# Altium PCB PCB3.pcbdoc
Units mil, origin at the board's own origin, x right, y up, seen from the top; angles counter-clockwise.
Board outline 9260 x 3292.5 mil, 4 copper layers (Top Layer, Inner1, Inner2, Bottom Layer); 89 components, 217 nets, 603 pads, 96 vias.
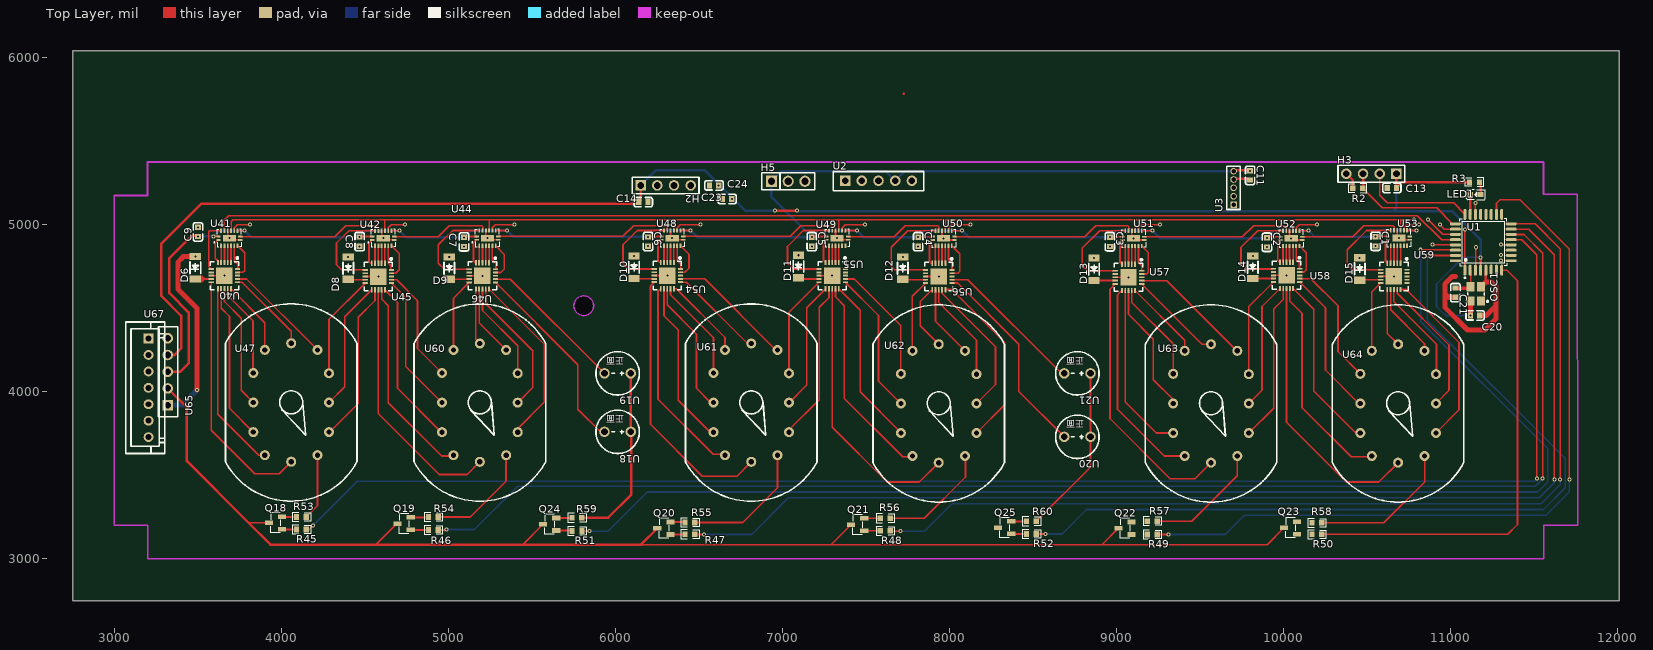
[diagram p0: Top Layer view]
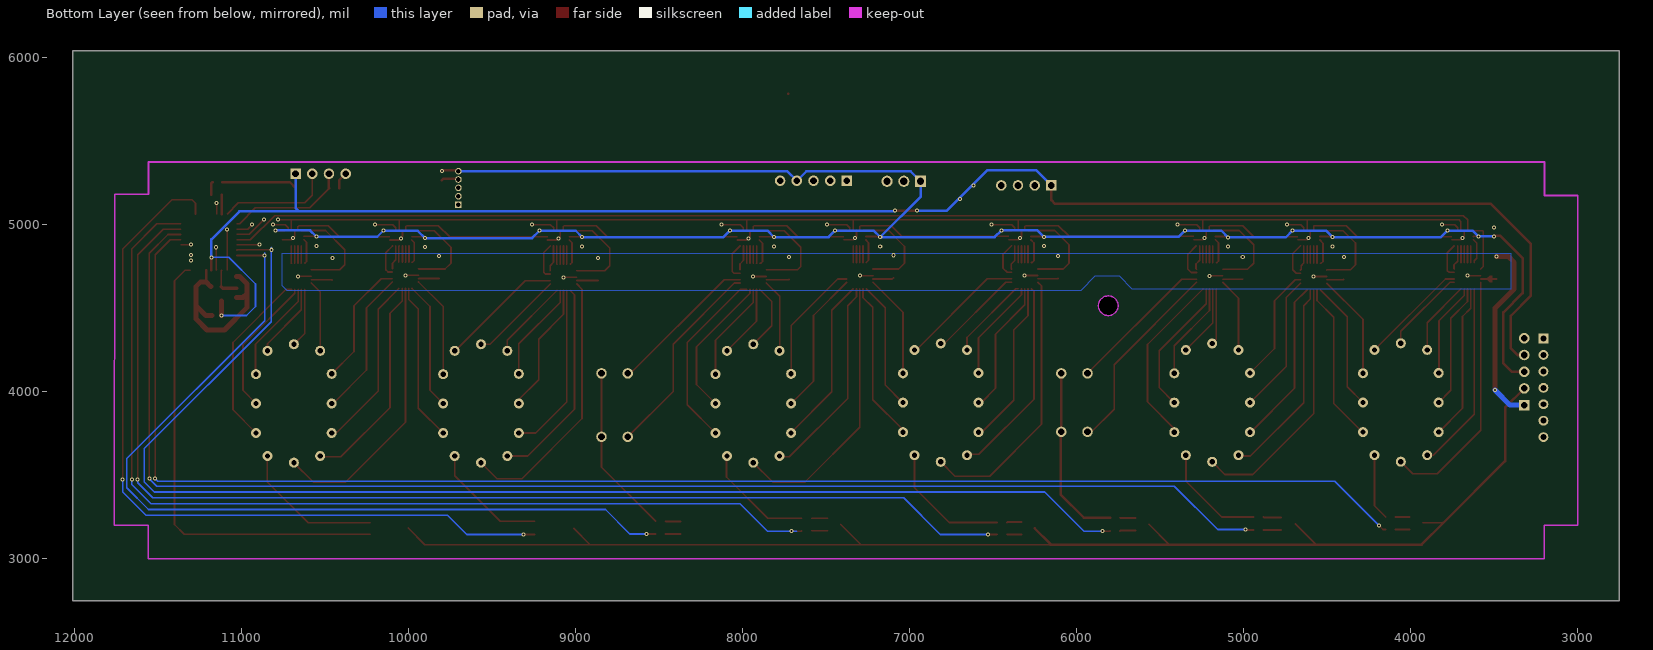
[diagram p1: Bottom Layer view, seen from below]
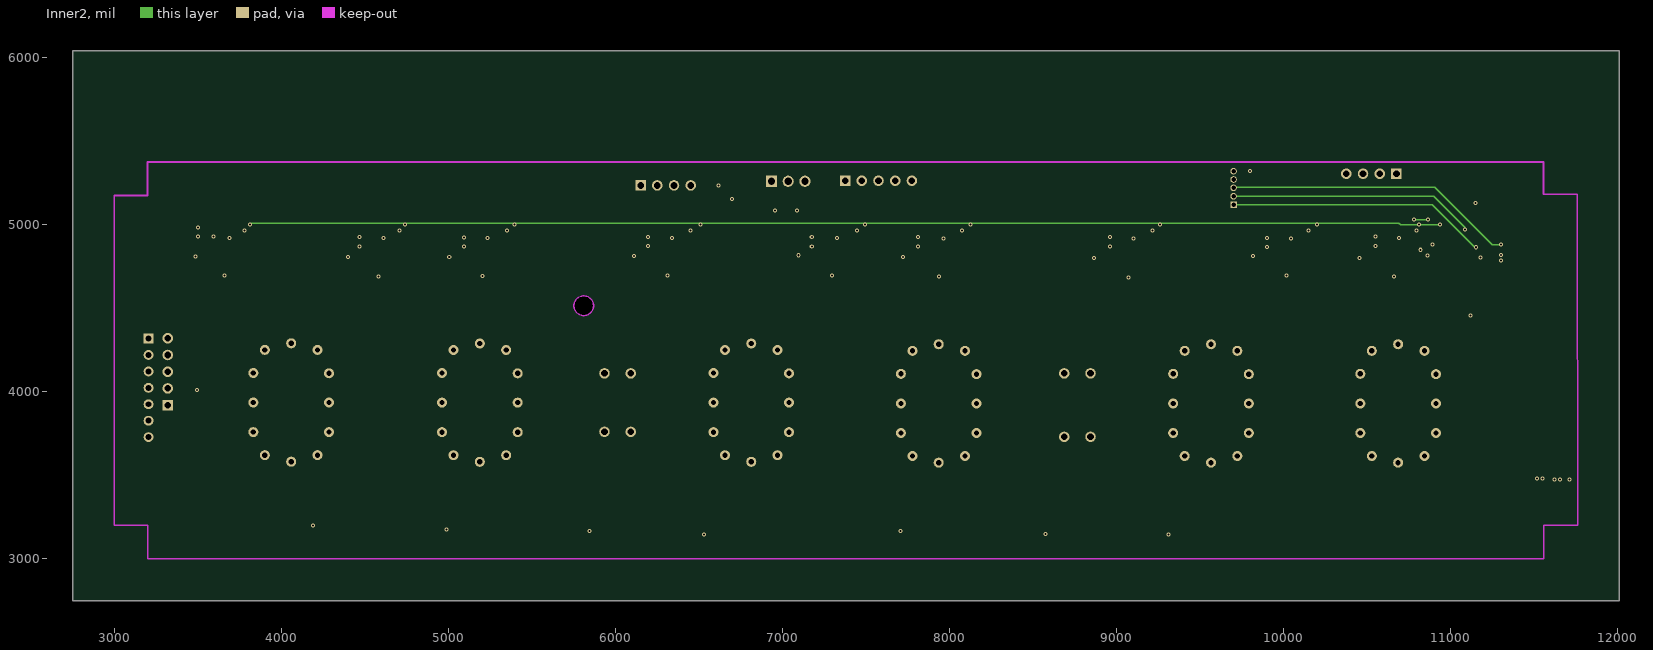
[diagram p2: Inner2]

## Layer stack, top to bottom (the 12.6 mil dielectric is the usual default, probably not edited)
Top Layer: signal copper (thickness not stored)
Dielectric: dielectric 12.6, FR-4, Dk 4.8
Inner1: signal copper (thickness not stored)
Dielectric: dielectric 12.6, FR-4, Dk 4.8
Inner2: signal copper (thickness not stored)
Dielectric: dielectric 12.6, FR-4, Dk 4.8
Bottom Layer: signal copper (thickness not stored)

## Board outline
12010,2750 2750,2750 2750,6042.5 12010,6042.5
cut-out: 5869.06,4515 cw(c5810,4515) 5750.94,4515 cw(c5810,4515)

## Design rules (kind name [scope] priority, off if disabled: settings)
BoardOutlineClearance copperThickness1oz [All] p0: genericclearance=10 ignorepadtopadclearanceinfootprint=FALSE except(0: Arc-SplitContinuation Track-SplitContinuation SMDPad-SplitContinuation THPad-SplitContinuation Via-SplitContinuation Fill-SplitContinuation Poly-SplitContinuation Region-SplitContinuation Text-SplitContinuation; 6: SMDPad-CutoutEdge THPad-CutoutEdge Via-CutoutEdge Fill-CutoutEdge Region-CutoutEdge; 11.8: Track-OutlineEdge SMDPad-OutlineEdge THPad-OutlineEdge Via-OutlineEdge Fill-OutlineEdge Region-OutlineEdge Poly-OutlineEdge Text-OutlineEdge Track-CutoutEdge)
BoardOutlineClearance copperThickness2oz [All] p0: genericclearance=10 ignorepadtopadclearanceinfootprint=FALSE except(0: Arc-SplitContinuation Track-SplitContinuation SMDPad-SplitContinuation THPad-SplitContinuation Via-SplitContinuation Fill-SplitContinuation Poly-SplitContinuation Region-SplitContinuation Text-SplitContinuation; 6: SMDPad-CutoutEdge THPad-CutoutEdge Via-CutoutEdge Fill-CutoutEdge Region-CutoutEdge; 11.8: Track-OutlineEdge SMDPad-OutlineEdge THPad-OutlineEdge Via-OutlineEdge Fill-OutlineEdge Region-OutlineEdge Poly-OutlineEdge Text-OutlineEdge Track-CutoutEdge)
Clearance copperThickness1oz [(InNet('GND') OR InNet('$1N6169') OR InNet('$1N6665') OR InNet('$1N6235') OR InNet('$1N6836') OR InNet('$1N6302') OR InNet('$1N6839') OR InNet('$1N6369') OR InNet('$1N6842') OR InNet('$1N6436') OR InNet('$1N6854') OR InNet('$1N6503') OR InNet('$1N6851') OR InNet('$1N6570') OR InNet('$1N6848') OR InNet('$1N6637') OR InNet('$1N6845') OR InNet('+5V') OR InNet('$1N7409') OR InNet('ADOT') OR InNet('NIX_A9') OR InNet('NIX_ADOT') OR InNet('$1N7759') OR InNet('$1N7768') OR InNet('NIX_A1') OR InNet('NIX_A2') OR InNet('NIX_A3') OR InNet('NIX_A4') OR InNet('NIX_A5') OR InNet('NIX_A6') OR InNet('NIX_A7') OR InNet('NIX_A8') OR InNet('A2') OR InNet('A3') OR InNet('A4') OR InNet('A5') OR InNet('A6') OR InNet('A7') OR InNet('$1N7662') OR InNet('NIX_A0') OR InNet('A0') OR InNet('A1') OR InNet('$1N7281') OR InNet('A8') OR InNet('A9') OR InNet('170V') OR InNet('SWITCH1') OR InNet('SWITCH2') OR InNet('SWITCH3') OR InNet('SWITCH4') OR InNet('SWITCH5') OR InNet('SWITCH6') OR InNet('COLON1') OR InNet('COLON2') OR InNet('A_HV') OR InNet('B_HV') OR InNet('C_HV') OR InNet('D_HV') OR InNet('E_HV') OR InNet('F_HV') OR InNet('G_HV') OR InNet('H_HV') OR InNet('CLK') OR InNet('CS') OR InNet('MOSI') OR InNet('BDOT') OR InNet('B1') OR InNet('B2') OR InNet('B3') OR InNet('B4') OR InNet('B7') OR InNet('B8') OR InNet('B9') OR InNet('B0') OR InNet('CDOT') OR InNet('C1') OR InNet('$1N12092') OR InNet('B5') OR InNet('B6') OR InNet('NIX_BDOT') OR InNet('NIX_B1') OR InNet('NIX_B2') OR InNet('NIX_B3') OR InNet('NIX_B4') OR InNet('NIX_B5') OR InNet('NIX_B6') OR InNet('NIX_B7') OR InNet('NIX_B8') OR InNet('NIX_B9') OR InNet('NIX_B0') OR InNet('NIX_CDOT') OR InNet('NIX_C1') OR InNet('C4') OR InNet('C5') OR InNet('C6') OR InNet('C7') OR InNet('C8') OR InNet('C9') OR InNet('$1N12107') OR InNet('C2') OR InNet('C3') OR InNet('D1') OR InNet('D2') OR InNet('D3') OR InNet('D4') OR InNet('D5') OR InNet('D6') OR InNet('$1N12114') OR InNet('C0') OR InNet('DDOT') OR InNet('D9') OR InNet('D0') OR InNet('EDOT') OR InNet('E1') OR InNet('E2') OR InNet('E3') OR InNet('$1N12123') OR InNet('D7') OR InNet('D8') OR InNet('E6') OR InNet('E7') OR InNet('E8') OR InNet('E9') OR InNet('E0') OR InNet('FDOT') OR InNet('$1N12132') OR InNet('E4') OR InNet('E5') OR InNet('F3') OR InNet('F4') OR InNet('F5') OR InNet('F6') OR InNet('F7') OR InNet('F8') OR InNet('$1N12137') OR InNet('F1') OR InNet('F2') OR InNet('F9') OR InNet('F0') OR InNet('$1N10205') OR InNet('$1N10207') OR InNet('$1N10209') OR InNet('$1N10723') OR InNet('$1N10725') OR InNet('$1N10727') OR InNet('+3.3V') OR InNet('RADER_RX') OR InNet('OSC_IN') OR InNet('RADER') OR InNet('NRST') OR InNet('LIGHT_ADC') OR InNet('BLE_TX') OR InNet('BLE_RX') OR InNet('SPI_MOSI') OR InNet('RADER_TX') OR InNet('POWER') OR InNet('I2C1_SCL') OR InNet('SPI_CS') OR InNet('I2C1_SDA') OR InNet('INFRARED-RAY') OR InNet('LED') OR InNet('SWDIO') OR InNet('SWCLK') OR InNet('DS3231') OR InNet('$2N1508') OR InNet('NIX_G0') OR InNet('NIX_G1') OR InNet('NIX_H0') OR InNet('NIX_H1') OR InNet('G0') OR InNet('G1') OR InNet('H0') OR InNet('H1') OR InNet('NIX_C2') OR InNet('NIX_C3') OR InNet('NIX_C4') OR InNet('NIX_C5') OR InNet('NIX_C6') OR InNet('NIX_C7') OR InNet('NIX_C8') OR InNet('NIX_C9') OR InNet('NIX_C0') OR InNet('NIX_DDOT') OR InNet('NIX_D1') OR InNet('NIX_D2') OR InNet('NIX_D3') OR InNet('NIX_D4') OR InNet('NIX_D5') OR InNet('NIX_D6') OR InNet('NIX_D7') OR InNet('NIX_D8') OR InNet('NIX_D9') OR InNet('NIX_D0') OR InNet('NIX_EDOT') OR InNet('NIX_E1') OR InNet('NIX_E2') OR InNet('NIX_E3') OR InNet('NIX_E4') OR InNet('NIX_E5') OR InNet('NIX_E6') OR InNet('NIX_E7') OR InNet('NIX_E8') OR InNet('NIX_E9') OR InNet('NIX_E0') OR InNet('NIX_FDOT') OR InNet('NIX_F1') OR InNet('NIX_F2') OR InNet('NIX_F3') OR InNet('NIX_F4') OR InNet('NIX_F5') OR InNet('NIX_F6') OR InNet('NIX_F7') OR InNet('NIX_F8') OR InNet('NIX_F9') OR InNet('NIX_F0') OR InNet('170_GND') OR InNet('SPI_SCK'))] p1: gap=7 ignorepadtopadclearanceinfootprint=FALSE except(4: Track-Track; 6: Track-SMDPad SMDPad-SMDPad Track-THPad SMDPad-THPad THPad-THPad Track-Via SMDPad-Via THPad-Via Via-Via Track-Fill SMDPad-Fill THPad-Fill Via-Fill Fill-Fill SMDPad-Region THPad-Region Via-Region Fill-Region Region-Region Track-Poly SMDPad-Poly THPad-Poly Via-Poly Fill-Poly Poly-Poly Track-Text SMDPad-Text THPad-Text Via-Text Fill-Text Region-Text Poly-Text Text-Text Track-Hole SMDPad-Hole THPad-Hole Via-Hole Fill-Hole Region-Hole Poly-Hole Text-Hole; 11.8: Track-Region Region-Poly Track-Sheet SMDPad-Sheet THPad-Sheet Via-Sheet Fill-Sheet Region-Sheet Poly-Sheet Text-Sheet Sheet-Hole)
Clearance copperThickness2oz [All] p1: gap=7 ignorepadtopadclearanceinfootprint=FALSE except(6: Track-SMDPad SMDPad-SMDPad Track-THPad SMDPad-THPad THPad-THPad Track-Via SMDPad-Via THPad-Via Via-Via Track-Fill SMDPad-Fill THPad-Fill Via-Fill Fill-Fill SMDPad-Region THPad-Region Via-Region Fill-Region Region-Region Track-Poly SMDPad-Poly THPad-Poly Via-Poly Fill-Poly Poly-Poly Track-Text SMDPad-Text THPad-Text Via-Text Fill-Text Region-Text Poly-Text Text-Text Track-Hole SMDPad-Hole THPad-Hole Via-Hole Fill-Hole Region-Hole Poly-Hole Text-Hole; 8: Track-Track; 11.8: Track-Region Region-Poly Track-Sheet SMDPad-Sheet THPad-Sheet Via-Sheet Fill-Sheet Region-Sheet Poly-Sheet Text-Sheet Sheet-Hole)
DiffPairsRouting differentialPair [All] p1: maxuncoupledlength=10 minlimit=6 maxlimit=6 mostfreqgap=6 toplayer_minwidth=5 toplayer_prefwidth=10 toplayer_maxwidth=100 bottomlayer_minwidth=5 bottomlayer_prefwidth=10 bottomlayer_maxwidth=100 midlayer1_minwidth=5 midlayer1_prefwidth=10 midlayer1_maxwidth=100 midlayer2_minwidth=5 midlayer2_prefwidth=10 midlayer2_maxwidth=100
PasteMaskExpansion pasteMaskExpansion [All] p1: expansion=0
PlaneConnect innerPlane [All] p1: planeconnectstyle=Relief reliefexpansion=20 reliefentries=4 reliefconductorwidth=10 reliefairgap=10
PolygonConnect copperRegion [All] p1: connectstyle=Relief reliefentries=4 reliefconductorwidth=10 polygonreliefangle="90 Angle" airgapwidth=10
RoutingVias viaSize [All] p1: viastyle="Through Hole" holewidth=12.0078 minholewidth=11.811 maxholewidth=248.0314 width=24.0158 minwidth=19.685 maxwidth=393.7008
SolderMaskExpansion solderMaskExpansion [All] p1: useseparateexpansions=TRUE expansion=2 expansionbottom=2
Width copperThickness1oz [All] p1: maxlimit=100 minlimit=5 preferedwidth=10
Width copperThickness2oz [All] p1: maxlimit=100 minlimit=8 preferedwidth=10

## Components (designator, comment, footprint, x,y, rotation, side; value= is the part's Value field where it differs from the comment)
C1 "CAP_0603" c0603 10550.22,4900.34 r270 top
C2 "CAP_0603" c0603 9900,4894.57 r270 top
C3 "CAP_0603" c0603 8959.25,4897.68 r270 top
C4 "CAP_0603" c0603 7812.28,4898 r270 top
C5 "CAP_0603" c0603 7175,4898 r270 top
C6 "CAP_0603" c0603 6195,4898.94 r270 top
C7 "CAP_0603" c0603 5093.22,4896.89 r270 top
C8 "CAP_0603" c0603 4468.27,4898.09 r270 top
C9 "CAP_0603" c0603 3500.75,4957.01 r90 top
C11 "CC0603KRX7R9BB104" c0603 9799.25,5294.66 r270 top
C13 "CC0603KRX7R9BB104" c0603 10647.09,5220 r180 top
C14 "CC0603KRX7R9BB104" c0603 6166.54,5135 r0 top
C20 "CC0603KRX7R9BB104" c0603 11146.56,4456.76 r0 top
C21 "CC0603KRX7R9BB104" c0603 11027.99,4592.82 r270 top
C23 "CC0603KRX7R9BB104" c0603 6668.68,5153.88 r0 top
C24 "CC0603KRX7R9BB104" c0603 6590,5235 r0 top
D6 "ZMM51" LL-34_L3.5-W1.5-RD 3485,4742.24 r90 top
D8 "ZMM51" LL-34_L3.5-W1.5-RD 4400,4740 r90 top
D9 "ZMM51" LL-34_L3.5-W1.5-RD 5005,4740 r90 top
D10 "ZMM51" LL-34_L3.5-W1.5-RD 6111.42,4745 r90 top
D11 "ZMM51" LL-34_L3.5-W1.5-RD 7095,4750 r90 top
D12 "ZMM51" LL-34_L3.5-W1.5-RD 7720,4740 r90 top
D13 "ZMM51" LL-34_L3.5-W1.5-RD 8865,4733.13 r90 top
D14 "ZMM51" LL-34_L3.5-W1.5-RD 9815,4745 r90 top
D15 "ZMM51" LL-34_L3.5-W1.5-RD 10455,4735 r90 top
H2 "排针" SIP-2.54MM-4P-CJT-H8.54 6300.49,5235 r180 top
H3 "排针" SIP-2.54MM-4P-CJT-H8.54 10525,5305 r0 top
H5 "PZ254V-11-03P" HDR-TH_3P-P2.54-V-M 7033.84,5260 r0 top
LED1 "NCD0603R1_C84263" LED0603-RD_RED 11147.74,5180 r0 top
OSC1 "OT2EL4C4JI-111OLP-8M" OSC-SMD_4P-L3.2-W2.5-BL-1 11150.5,4585.77 r90 top
Q18 "13001_C2904842" SOT-23-3_L2.9-W1.3-P1.90-LS2.4-BR 3965,3215 r0 top
Q19 "13001_C2904842" SOT-23-3_L2.9-W1.3-P1.90-LS2.4-BR 4735,3210.16 r0 top
Q20 "13001_C2904842" SOT-23-3_L2.9-W1.3-P1.90-LS2.4-BR 6290,3182.98 r0 top
Q21 "13001_C2904842" SOT-23-3_L2.9-W1.3-P1.90-LS2.4-BR 7450,3205 r0 top
Q22 "13001_C2904842" SOT-23-3_L2.9-W1.3-P1.90-LS2.4-BR 9050,3182.98 r0 top
Q23 "13001_C2904842" SOT-23-3_L2.9-W1.3-P1.90-LS2.4-BR 10040.78,3185 r0 top
Q24 "13001_C2904842" SOT-23-3_L2.9-W1.3-P1.90-LS2.4-BR 5605.8,3206.69 r0 top
Q25 "13001_C2904842" SOT-23-3_L2.9-W1.3-P1.90-LS2.4-BR 8330,3186.3 r0 top
R2 "0805W8F1002T5E_C17414" r0603 10442.93,5217.87 r0 top
R3 "0805W8F1002T5E_C17414" r0603 11142.53,5255 r0 top
R45 "Res_0603" r0603 4120.06,3175 r180 top
R46 "Res_0603" r0603 4910,3172.6 r180 top
R47 "Res_0603" r0603 6445.8,3147.35 r180 top
R48 "Res_0603" r0603 7615,3167.05 r180 top
R49 "Res_0603" r0603 9213.04,3145.58 r180 top
R50 "Res_0603" r0603 10198.67,3146.37 r180 top
R51 "Res_0603" r0603 5769.61,3166.06 r180 top
R52 "Res_0603" r0603 8490,3148.9 r180 top
R53 "Res_0603" r0603 4120.06,3250.63 r180 top
R54 "Res_0603" r0603 4910,3249.96 r180 top
R55 "Res_0603" r0603 6445.8,3217.15 r180 top
R56 "Res_0603" r0603 7615,3243.3 r180 top
R57 "Res_0603" r0603 9213.04,3225.38 r180 top
R58 "Res_0603" r0603 10198.67,3215 r180 top
R59 "Res_0603" r0603 5769.23,3245.86 r180 top
R60 "Res_0603" r0603 8490,3224.62 r180 top
U1 "STM32G070KBT6" LQFP-32_L7.0-W7.0-P0.80-LS9.0-BL 11195,4894.57 r0 top
U2 "2.54mm1*5" 2.54mm1*5 7574.51,5263.03 r0 top
U3 "FH1.27-01-5PZD" HDR-TH_5P-P1.27-V-M 9700,5220.54 r90 top
U18 "氖泡" 6*13氖泡 6012.99,3760 r180 top
U19 "氖泡" 6*13氖泡 6012.99,4110 r180 top
U20 "氖泡" 6*13氖泡 8765,3730 r180 top
U21 "氖泡" 6*13氖泡 8765,4110 r180 top
U40 "ULN2803A_C493377" QFN-20_L4.0-W4.0-P0.50-BL-EP 3659.33,4695 r180 top
U41 "74HC595BQ,115" DHVQFN-16_L3.5-W2.5-P0.50-BL-EP 3688.86,4919.05 r0 top
U42 "74HC595BQ,115" DHVQFN-16_L3.5-W2.5-P0.50-BL-EP 4610,4919.05 r0 top
U44 "74HC595BQ,115" DHVQFN-16_L3.5-W2.5-P0.50-BL-EP 5233.81,4919.6 r0 top
U45 "ULN2803A_C493377" QFN-20_L4.0-W4.0-P0.50-BL-EP 4580.47,4689.72 r180 top
U46 "ULN2803A_C493377" QFN-20_L4.0-W4.0-P0.50-BL-EP 5203.62,4694.06 r180 top
U47 "IN12" IN12 4058.8,3935.63 r0 top
U48 "74HC595BQ,115" DHVQFN-16_L3.5-W2.5-P0.50-BL-EP 6339.68,4920 r0 top
U49 "74HC595BQ,115" DHVQFN-16_L3.5-W2.5-P0.50-BL-EP 7327.11,4919.33 r0 top
U50 "74HC595BQ,115" DHVQFN-16_L3.5-W2.5-P0.50-BL-EP 7964.25,4918.67 r0 top
U51 "74HC595BQ,115" DHVQFN-16_L3.5-W2.5-P0.50-BL-EP 9101.1,4918.35 r0 top
U52 "74HC595BQ,115" DHVQFN-16_L3.5-W2.5-P0.50-BL-EP 10045,4918.35 r0 top
U53 "74HC595BQ,115" DHVQFN-16_L3.5-W2.5-P0.50-BL-EP 10690,4920.16 r0 top
U54 "ULN2803A_C493377" QFN-20_L4.0-W4.0-P0.50-BL-EP 6310.15,4695.42 r180 top
U55 "ULN2803A_C493377" QFN-20_L4.0-W4.0-P0.50-BL-EP 7297.58,4695 r180 top
U56 "ULN2803A_C493377" QFN-20_L4.0-W4.0-P0.50-BL-EP 7935.32,4690 r180 top
U57 "ULN2803A_C493377" QFN-20_L4.0-W4.0-P0.50-BL-EP 9070.91,4685 r180 top
U58 "ULN2803A_C493377" QFN-20_L4.0-W4.0-P0.50-BL-EP 10017.32,4696.79 r180 top
U59 "ULN2803A_C493377" QFN-20_L4.0-W4.0-P0.50-BL-EP 10659.81,4690.5 r180 top
U60 "IN12" IN12 5188,3935 r0 top
U61 "IN12" IN12 6812.88,3935 r0 top
U62 "IN12" IN12 7935,3930 r0 top
U63 "IN12" IN12 9565,3930 r0 top
U64 "IN12" IN12 10685,3930 r0 top
U65 "2.54mm1*5" 2.54mm1*5 3320,4120 r90 top
U67 "HX 2.54mm-7P ZZ" CONN-TH_7P-P2.50_HX-2.54MM-7P-ZZ 3205,4023.54 r270 top

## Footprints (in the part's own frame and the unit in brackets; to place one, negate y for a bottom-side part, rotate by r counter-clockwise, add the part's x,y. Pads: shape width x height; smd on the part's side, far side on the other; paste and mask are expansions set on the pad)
2.54mm1*5 [mm]
  rect 1.6x1.6 hole 1: 1(-5.08,0)
  round 1.6 hole 1: 2(-2.54,0) 3(0,0) 4(2.54,0) 5(5.08,0)
  silkscreen extent -6.86,-1.52 6.86,1.4
6*13氖泡 [mm]
  round 1.6 hole 1: 1(-2,0) 2(2,0)
  silkscreen extent -3.3,-3.3 3.3,3.3
c0603 [mm]
  rect 0.8x0.9 smd: 1(-0.7,0) 2(0.7,0)
  silkscreen extent -1.41,-0.71 1.39,0.72
CONN-TH_7P-P2.50_HX-2.54MM-7P-ZZ [mm]
  rect 1.5x1.5 hole 0.9: 1(-7.5,0)
  round 1.5 hole 0.9: 2(-5,0) 3(-2.5,0) 4(0,0) 5(2.5,0) 6(5,0) 7(7.5,0)
  silkscreen extent -10,-3.46 10,2.44
DHVQFN-16_L3.5-W2.5-P0.50-BL-EP [mm]
  rect 0.665x0.28 smd: 1(-1.658,-0.25) 8(1.658,-0.25) 9(1.658,0.25) 16(-1.658,0.25)
  rect 0.28x0.665 smd: 2(-1.25,-1.157) 3(-0.75,-1.157) 4(-0.25,-1.157) 5(0.25,-1.157) 6(0.75,-1.157) 7(1.25,-1.157) 10(1.25,1.157) 11(0.75,1.157) 12(0.25,1.157) 13(-0.25,1.157) 14(-0.75,1.157) 15(-1.25,1.157)
  rect 2x1 smd: 17(0,0)
  silkscreen extent -2.36,-1.33 1.83,1.33
HDR-TH_3P-P2.54-V-M [mm]
  rect 1.7x1.7 hole 1.1: 1(-2.54,0)
  round 1.7 hole 1.1: 2(0,0) 3(2.54,0)
  silkscreen extent -4.02,-1.27 4.02,1.27
HDR-TH_5P-P1.27-V-M [mm]
  rect 1x1 hole 0.7: 1(-2.54,0)
  round 1 hole 0.7: 2(-1.27,0) 3(0,0) 4(1.27,0) 5(2.54,0)
  silkscreen extent -3.3,-1.02 3.3,1.02
IN12 [mil]
  round 60 hole 31.5: 0(226.4,-177.2) 1(-157.5,-315) 2(-226.4,-177.2) 3(-226.4,0) 4(-226.4,177.2) 5(-157.5,315) 6(0,354.3) 7(157.5,315) 8(226.4,175) 9(226.4,0) DOT(0,-354.3) HV(157.5,-315)
  silkscreen extent -394,-591 394,591
LED0603-RD_RED [mm]
  rect 0.8x0.8 smd: 1(-0.8,-0.003) 2(0.8,0.003)
  silkscreen extent -1.49,-0.75 1.39,0.76
LL-34_L3.5-W1.5-RD [mm]
  rect 1.1x1.7 smd: 1(-1.7,0) 2(1.7,0)
  silkscreen extent -0.9,-0.8 0.9,0.8
LQFP-32_L7.0-W7.0-P0.80-LS9.0-BL [mm]
  oval 0.448x1.684 smd: 1(-2.8,-4.242) 2(-2,-4.242) 3(-1.2,-4.242) 4(-0.4,-4.242) 5(0.4,-4.242) 6(1.2,-4.242) 7(2,-4.242) 8(2.8,-4.242) 17(2.8,4.242) 18(2,4.242) 19(1.2,4.242) 20(0.4,4.242) 21(-0.4,4.242) 22(-1.2,4.242) 23(-2,4.242) 24(-2.8,4.242)
  oval 1.684x0.448 smd: 9(4.242,-2.8) 10(4.242,-2) 11(4.242,-1.2) 12(4.242,-0.4) 13(4.242,0.4) 14(4.242,1.2) 15(4.242,2) 16(4.242,2.8) 25(-4.242,2.8) 26(-4.242,2) 27(-4.242,1.2) 28(-4.242,0.4) 29(-4.242,-0.4) 30(-4.242,-1.2) 31(-4.242,-2) 32(-4.242,-2.8)
  silkscreen extent -3.58,-5.48 3.58,3.58
OSC-SMD_4P-L3.2-W2.5-BL-1 [mm]
  rect 1.4x1.2 smd: 1(-1.1,-0.8) 2(1.1,-0.8) 3(1.1,0.8) 4(-1.1,0.8)
  silkscreen extent -1.27,-1.91 0.17,1.25
QFN-20_L4.0-W4.0-P0.50-BL-EP [mm]
  rect 0.28x0.8 smd: 1(-1,-2) 2(-0.5,-2) 3(0,-2) 4(0.5,-2) 5(1,-2) 11(1,2) 12(0.5,2) 13(0,2) 14(-0.5,2) 15(-1,2)
  rect 0.8x0.28 smd: 6(2,-1) 7(2,-0.5) 8(2,0) 9(2,0.5) 10(2,1) 16(-2,1) 17(-2,0.5) 18(-2,0) 19(-2,-0.5) 20(-2,-1)
  rect 2.5x2.5 smd: 21(0,0)
  silkscreen extent -2.15,-2.82 2.15,2.15
r0603 [mil]
  rect 31.75x34.02 smd: 1(-29.66,0) 2(29.66,0)
  silkscreen extent -55,-26 55,26
SIP-2.54MM-4P-CJT-H8.54 [mm]
  rect 1.6x1.6 hole 1.02: 1(3.81,0)
  round 1.6 hole 1.02: 2(1.27,0) 3(-1.27,0) 4(-3.81,0)
  silkscreen extent -5.08,-1.27 5.08,1.27
SOT-23-3_L2.9-W1.3-P1.90-LS2.4-BR [mm]
  rect 1.25x0.7 smd: 1(1,-0.95) 2(1,0.95) 3(-1,0)
  silkscreen extent -0.73,-1.53 0.73,1.53

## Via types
v1: diameter 24.02, hole 12.01, Top Layer to Bottom Layer, 96 vias

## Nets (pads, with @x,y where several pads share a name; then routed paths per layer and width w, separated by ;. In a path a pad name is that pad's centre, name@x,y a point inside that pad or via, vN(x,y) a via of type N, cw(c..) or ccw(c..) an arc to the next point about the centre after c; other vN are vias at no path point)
170_GND: D6.2 D8.2 D9.2 D10.2 D11.2 D12.2 D13.2 D14.2 D15.2 U40.8 U40.21 U45.8 U45.21 U46.8 U46.21 U54.8 U54.21 U55.8 U55.21 U56.8 U56.21 U57.8 U57.21 U58.8 U58.21 U59.8 U59.21 U65.1 | length 1852.7
  Top Layer w10: U40.8 v1(3659.33,4695) ; U45.8 v1(4580.47,4689.72) ; U46.8 v1(5203.62,4694.06) ; U54.8 v1(6310.15,4695.42) ; U55.8 v1(7297.58,4695) ; U56.8 U56.21 ; U57.8 v1(9070.91,4685) ; U58.8 v1(10017.32,4696.79) ; U59.8 v1(10659.81,4690.5)
  Top Layer w30: D6.2 3414.17,4809.17 3380,4775 3380,4615 3495,4500 v1(3495,4010)
  Bottom Layer w30: U65.1 3405,3920 v1(3495,4010)
  other v1: 7935.32,4690.42 8865.29,4800.24 10455,4801.93 4400.18,4806.64 5005,4806.93 7720,4806.93 3485.29,4809.35 6111.7,4812.11 9815.29,4812.11 7095.29,4817.11
170V: Q18.3 Q19.3 Q20.3 Q21.3 Q22.3 Q23.3 Q24.3 Q25.3 U65.2 | length 8212.4
  Top Layer w10: 3805,3215 Q18.3 ; 4565.72,3085 Q19.3@4690.63,3209.91 ; 5444.74,3085 Q24.3 ; 6155.97,3085 7290.63,3085 ; Q21.3 7290.63,3085 ; Q22.3 8912.65,3085 ; Q23.3 9901.41,3085 8912.65,3085 ; 7290.63,3085 8912.65,3085
  Top Layer w15: U65.2 3435,3905 3435,3585 3805,3215 3935,3085 4565.72,3085 5444.74,3085 6155.97,3085 6155.97,3088.32 Q20.3
$1N6169: Q18.1 R45.2 | length 87.1
  Top Layer w10: Q18.1 4006.97,3175 R45.2
$1N6235: Q19.1 R46.2 | length 106
  Top Layer w10: Q19.1 4880.18,3172.76 R46.2
$1N6302: Q20.1 R47.2 | length 87.5
  Top Layer w10: Q20.1 6414.37,3145.58 R47.2
$1N6369: Q21.1 R48.2 | length 96.2
  Top Layer w10: Q21.1 7584.79,3167.6 R48.2
$1N6436: Q22.1 R49.2
$1N6503: Q23.1 R50.2
$1N6570: Q24.1 R51.2 | length 96.1
  Top Layer w10: Q24.1 5736.72,3169.29 R51.2
$1N6637: Q25.1 R52.2 | length 91
  Top Layer w10: Q25.1 R52.2
$1N6665: Q18.2 R53.2 | length 86.8
  Top Layer w10: Q18.2 4006.14,3250.63 R53.2
$1N6836: Q19.2 R54.2 | length 107
  Top Layer w10: Q19.2 4877.94,3247.56 R54.2
$1N6839: Q20.2 R55.2 | length 88.1
  Top Layer w10: Q20.2 6412.91,3220.38 R55.2
$1N6842: Q21.2 R56.2 | length 96.3
  Top Layer w10: Q21.2 7584.44,3242.4 R56.2
$1N6845: Q25.2 R60.2 | length 91.4
  Top Layer w10: Q25.2 8459.42,3223.7 R60.2
$1N6848: Q24.2 R59.2 | length 95.1
  Top Layer w10: Q24.2 5737.8,3244.09 R59.2
$1N6851: Q23.2 R58.2
$1N6854: Q22.2 R57.2
$1N7281: U41.9 U42.14 | length 881.9
  Top Layer w8: U41.9 4318.89,4928.89 4385,4995 4576.77,4995 4580.47,4991.3 U42.14
$1N7409: U42.9 U44.14 | length 583.2
  Top Layer w8: U42.9 4938.89,4928.89 5005,4995 5199.04,4995 5204.28,4989.75 U44.14
$1N7662: D6.1 U40.9 | length 98.8
  Top Layer w10: D6.1@3485,4673.07 D6.1@3487.24,4675.31 ; D6.1 D6.1@3487.24,4675.31 ; U40.9 D6.1@3487.24,4675.31
$1N7759: D8.1 U45.9 | length 103
  Top Layer w10: D8.1 4403.04,4670.03 U45.9
$1N7768: D9.1 U46.9 | length 120.4
  Top Layer w10: D9.1 5006.3,4674.36 U46.9
$1N10205: D10.1 U54.9 | length 121
  Top Layer w10: D10.1 6113.76,4675.73 U54.9
$1N10207: D11.1 U55.9 | length 127.1
  Top Layer w10: D11.1 7102.76,4675.31 U55.9
$1N10209: D12.1 U56.9 | length 137.7
  Top Layer w10: D12.1 7722.76,4670.31 U56.9
$1N10723: D13.1 U57.9 | length 127.5
  Top Layer w10: D13.1 8991.28,4666.2 U57.9
$1N10725: D14.1 U58.9 | length 124
  Top Layer w10: D14.1 9937.61,4678.07 U58.9
$1N10727: D15.1 U59.9 | length 127.2
  Top Layer w10: D15.1 10457.74,4670.81 U59.9
$1N12092: U44.9 U48.14 | length 1064.6
  Top Layer w8: U44.9 6044.44,4929.44 6110,4995 6305,4995 6310,4990 6310,4965.72 U48.14
$1N12107: U48.9 U49.14 | length 946.9
  Top Layer w8: U48.9 7044.84,4929.84 7110,4995 7292.68,4995 7297.58,4990.1 U49.14
$1N12114: U49.9 U50.14 | length 598.1
  Top Layer w8: U49.9 7669.17,4929.17 7735,4995 7930.35,4995 7935,4990.35 7935,4964.51 U50.14
$1N12123: U50.9 U51.14 | length 1098.2
  Top Layer w8: U50.9 8808.51,4928.51 8875,4995 9067.35,4995 9071.57,4990.78 U51.14
$1N12132: U51.9 U52.14 | length 904.7
  Top Layer w8: U51.9 9753.19,4928.19 9820,4995 10010,4995 10015.47,4989.53 U52.14
$1N12137: U52.9 U53.14 | length 603.3
  Top Layer w8: U52.9 10413.19,4928.19 10480,4995 10653.89,4995 10660.47,4988.42 U53.14
$2N1508: LED1.2 R3.2 | length 77.8
  Top Layer w15: R3.2 11179.22,5247.97 LED1.2
+3.3V: C13.1 C14.1 C20.1 C23.2 C24.2 H2.1 H3.1 OSC1.4 R3.1 U1.4 U65.4 | length 10818.7
  Top Layer w15: U65.4 3360,4220 3400,4260 3400,4455 3280,4575 3280,4885 3520,5125 6128.26,5125 6150.49,5147.23 H2.1 ; v1(6954.46,5084.49) v1(7087.28,5084.49) ; C13.1@10673.98,5210 10673.98,5303.98 H3.1 ; C13.1 10709.65,5255 R3.1 ; U1.4@11179.25,4728.08 v1(11179.25,4804.25) v1@11180,4805
  Top Layer w30: v1(11119,4456.76) OSC1.4
  Bottom Layer w10: v1(11119,4456.76) 10968.24,4456.76 10915,4510 10915,4645 11074.25,4804.25 v1(11179.25,4804.25)
  Bottom Layer w15: H2.1 6240.49,5325 6535,5325 6775.51,5084.49 v1(6954.46,5084.49) ; v1(7087.28,5084.49) 7091.77,5080 10655,5080 ; H3.1 10675,5100 10655,5080 ; v1(11179.25,4804.25) 11179.25,4912.04 11011.29,5080 10655,5080
  other v1: 6696.24,5153.88 6617.56,5235
+5V: C1.1 C2.1 C3.1 C4.1 C5.1 C6.1 C7.1 C8.1 C9.1 C11.1 H5.1 U2.4 U3.5 U41.10 U41.16 U42.10 U42.16 U44.10 U44.16 U48.10 U48.16 U49.10 U49.16 U50.10 U50.16 U51.10 U51.16 U52.10 U52.16 U53.10 U53.16 U65.3 | length 13207.1
  Top Layer w10: v1(3595,4930) 3622.49,4930 U41.16 ; U41.10 3779.62,4964.62 v1(3780,4965) ; v1(4468.27,4925.65) 4471.51,4928.89 U42.16 ; U42.10 v1(4707.54,4964.62) ; v1(5093.22,4924.45) 5098.21,4929.44 U44.16 ; U44.10 v1(5350,4965.17) ; v1(6195,4926.5) 6198.34,4929.84 U48.16 ; U48.10 v1(6450,4965.57) ; v1(7175,4925.56) 7178.61,4929.17 U49.16 ; U49.10 v1(7445,4964.9) ; v1(7812.28,4925.56) 7815.23,4928.51 U50.16 ; U50.10 v1(8075,4964.24) ; v1(8959.25,4925.24) 8962.2,4928.19 U51.16 ; U51.10 v1(9215,4963.92) ; v1(9900,4920) 9908.19,4928.19 U52.16 ; U52.10 v1(10150,4963.92) ; v1(10550.22,4927.9) 10552.32,4930 U53.16 ; U53.10 v1(10795,4965.73)
  Top Layer w15: U65.3 3395,4120 3445,4170 3445,4475 3330,4590 3330,4800 3465,4935 3495.2,4935 v1(3500.75,4929.45) ; 7725,5782.56 7725,5785 ; U3.5@9700,5325 9796.48,5325 v1(9799.25,5322.23)
  Bottom Layer w15: v1(3500.75,4929.45) 3501.3,4930 v1(3595,4930) 3630,4965 v1(3780,4965) 3819.35,4925.65 v1(4468.27,4925.65) 4507.24,4964.62 v1(4707.54,4964.62) 4747.71,4924.45 v1(5093.22,4924.45) 5133.94,4965.17 v1(5350,4965.17) 5388.68,4926.5 v1(6195,4926.5) 6234.07,4965.57 v1(6450,4965.57) 6490.01,4925.56 v1(7175,4925.56) ; H5.1@6933.84,5265 H5.1 ; U3.5 7732.02,5320.54 U2.4 7617.54,5320 6993.84,5320 H5.1 ; v1(10795,4965.73) 10588.05,4965.73 v1(10550.22,4927.9) 10186.02,4927.9 v1(10150,4963.92) 9943.92,4963.92 v1(9900,4920) 9258.92,4920 v1(9215,4963.92) 8997.93,4963.92 v1(8959.25,4925.24) 8114,4925.24 v1(8075,4964.24) 7850.96,4964.24 v1(7812.28,4925.56) 7484.34,4925.56 v1(7445,4964.9) 7214.34,4964.9 v1(7175,4925.56) ; H5.1 6933.84,5166.72 v1(7175,4925.56)
A0: U42.2 U45.4 | length 105
  Top Layer w10: U45.4 U42.2
A1: U40.5 U41.1 | length 149.4
  Top Layer w10: U40.5 3619.96,4785.04 3605,4800 3605,4890.62 U41.1
A2: U40.4 U41.2 | length 99.7
  Top Layer w10: U40.4@3639.65,4773.75 U41.2
A3: U40.3 U41.3 | length 99.7
  Top Layer w10: U40.3 U41.3
A4: U40.2 U41.4 | length 99.7
  Top Layer w10: U40.2@3679.02,4773.75 U41.4
A5: U40.1 U41.5 | length 99.7
  Top Layer w10: U40.1 U41.5
A6: U40.20 U41.6 | length 148.9
  Top Layer w10: U41.6 3718.39,4781.61 3740,4760 3740,4736.3 U40.20
A7: U40.19 U41.7 | length 212.1
  Top Layer w10: U40.19 3769.68,4714.68 3780,4725 3780,4831.55 U41.7
A8: U42.15 U45.6 | length 576.2
  Top Layer w10: U45.6 4500.82,4730 4360,4730 4330,4760 4330,4890 4404.62,4964.62 U42.15
A9: U42.1 U45.5 | length 158.3
  Top Layer w10: U45.5 4536.54,4768.46 4525,4780 4525,4889.47 U42.1
A_HV: R53.1 U47.HV | length 397.6
  Top Layer w10: R53.1 4216.3,3317.21 U47.HV
ADOT: U40.6 U41.15 | length 308.7
  Top Layer w10: U40.6 3565,4749.96 3565,4960.14 3569.49,4964.62 U41.15
B0: U44.5 U46.1 | length 101.5
  Top Layer w10: U46.1 5243.65,4773.46 U44.5
B1: U42.4 U45.2 | length 105
  Top Layer w10: U45.2 U42.4
B2: U42.5 U45.1 | length 105
  Top Layer w10: U45.1 U42.5
B3: U42.6 U45.20 | length 152.5
  Top Layer w10: U42.6 4639.53,4770.47 4655,4755 4655,4733.3 U45.20
B4: U42.7 U45.19 | length 216.8
  Top Layer w10: U45.19 4659.81,4710 4685,4710 4705,4730 4705,4827.69 U42.7
B5: U44.15 U46.6 | length 589.9
  Top Layer w10: U46.6 4976.57,4733.43 4940,4770 4940,4880 5025.17,4965.17 U44.15
B6: U44.1 U46.5 | length 153
  Top Layer w10: U46.5 5160,4772.8 5150,4782.8 5150,4891.21 U44.1
B7: U44.2 U46.4 | length 101.5
  Top Layer w10: U46.4 5184.6,4773.47 U44.2
B8: U44.3 U46.3 | length 101.5
  Top Layer w10: U46.3 5204.28,4773.46 U44.3
B9: U44.4 U46.2 | length 101.5
  Top Layer w10: U46.2 5223.98,4773.47 U44.4
B_HV: R54.1 U60.HV | length 649.6
  Top Layer w10: R54.1 5129.96,3249.96 5345,3465 5345,3619.5 U60.HV
BDOT: U42.3 U45.3 | length 105
  Top Layer w10: U45.3 U42.3
BLE_RX: H2.3 U1.10
BLE_TX: H2.2 U1.9
C0: U49.2 U55.4 | length 100
  Top Layer w10: U55.4@7277.9,4773.75 U49.2
C1: U48.1 U54.5 | length 154
  Top Layer w10: U54.5 6265,4774.16 6255,4784.16 6255,4890.74 U48.1
C2: U48.2 U54.4 | length 100.3
  Top Layer w10: U54.4 U48.2
C3: U48.3 U54.3 | length 100.3
  Top Layer w10: U54.3 U48.3
C4: U48.4 U54.2 | length 100.3
  Top Layer w10: U54.2 U48.4
C5: U48.5 U54.1 | length 100.3
  Top Layer w10: U54.1 U48.5
C6: U48.6 U54.20 | length 148.7
  Top Layer w10: U48.6 6369.21,4785.79 6390,4765 6390,4735.9 U54.20
C7: U48.7 U54.19 | length 217.1
  Top Layer w10: U54.19 6388.99,4715 6415,4715 6440,4740 6440,4823.32 U48.7
C8: U49.15 U55.6 | length 590.8
  Top Layer w10: U55.6 7218.21,4735 7065,4735 7030,4770 7030,4870 7124.9,4964.9 U49.15
C9: U49.1 U55.5 | length 148.2
  Top Layer w10: U55.5 7245,4786.95 7245,4892.64 U49.1
C_HV: R55.1 U61.HV | length 775.8
  Top Layer w10: R55.1 6762.15,3217.15 6970,3425 6970,3619.62 U61.HV
CDOT: U48.15 U54.6 | length 591.9
  Top Layer w10: U54.6 6231.2,4735 6080,4735 6045,4770 6045,4880 6130.57,4965.57 U48.15
CLK: U1.26 U41.11 U42.11 U44.11 U48.11 U49.11 U50.11 U51.11 U52.11 U53.11 | length 8560.5
  Top Layer w8: U41.11 3718.39,4981.71 3736.67,5000 v1(3812.85,5000) ; U42.11 4639.53,4981.71 4657.82,5000 v1(4740,5000) ; U44.11 5263.35,4982.26 5281.08,5000 v1(5395,5000) ; U48.11 6369.21,4982.66 6386.55,5000 v1(6510,5000) ; U49.11 7356.64,4981.99 7374.65,5000 v1(7495,5000) ; U50.11 7993.78,4981.33 8012.46,5000 v1(8125,5000) ; U51.11 9130.63,4981.01 9149.63,5000 v1(9260,5000) ; U52.11 10074.53,4981.01 10093.52,5000 v1(10200,5000) ; U53.11 10719.53,4982.82 10736.71,5000 v1(10810,5000) ; v1(10935,5000) 10961.17,4973.83 U1.26@11027.99,4973.83
  Inner2 w8: v1(3812.85,5000) 3822.85,5010 4730,5010 v1(4740,5000) 4750,5010 5385,5010 v1(5395,5000) ; v1@5395,5010 10690,5010 10700,5000 v1(10810,5000) v1(10935,5000)
  Bottom Layer w8: v1(10810,5000) v1@10810,5010
COLON1: R51.1 U1.30 | length 7832.3
  Top Layer w10: R51.1 5800.33,3165 v1(5845,3165) ; v1(10820,4850) 11025.32,4850 U1.30
  Bottom Layer w10: v1(5845,3165) 5955,3165 6190,3400 11520,3400 11580,3460 11580,3660 10820,4420 v1(10820,4850) 10820,4865
COLON2: R52.1 U1.31 | length 5195.2
  Top Layer w10: R52.1 v1(8575,3148.9) ; v1(10860,4815.83) U1.31
  Bottom Layer w10: v1(8575,3148.9) 8673.9,3148.9 8820,3295 11555,3295 11685,3425 11685,3600 10860,4425 v1(10860,4815.83) 10860,4830.83
CS: U1.27 U41.12 U42.12 U44.12 U48.12 U49.12 U50.12 U51.12 U52.12 U53.12 | length 7912.2
  Top Layer w8: U41.12@3698.7,4969.62 3698.7,5018.7 3709.84,5029.84 5245,5029.84 ; U42.12 4619.84,5024.84 4620,5025 ; U44.12@5243.65,4970.17 5245,4971.52 5245,5029.84 ; U48.12@6349.52,4970.57 6349.52,5029.52 6349.84,5029.84 ; U49.12@7336.95,4969.9 7336.95,5030 ; U50.12@7974.09,4969.24 7974.09,5030 ; U51.12 9110.94,5029.06 9110,5030 ; U52.12@10054.84,4968.92 10054.84,5030 ; U53.12 10700,4965.89 10700,5030 ; v1(10780,5030) 10700,5030 ; v1(10865,5030) 10952.67,4942.33 U1.27@11027.99,4942.33 ; 5245,5029.84 6349.84,5029.84 ; 6349.84,5029.84 6350,5030 7336.95,5030 ; 7336.95,5030 7974.09,5030 ; 7974.09,5030 9110,5030 ; 9110,5030 10054.84,5030 ; 10054.84,5030 10700,5030
  Inner2 w8: v1(10780,5030) v1(10865,5030)
D0: U50.5 U56.1 | length 104.2
  Top Layer w10: U50.5 7974.09,4769.76 U56.1@7974.69,4769.16
D1: U49.4 U55.2 | length 100
  Top Layer w10: U55.2@7317.27,4773.75 U49.4
D2: U49.5 U55.1 | length 100
  Top Layer w10: U55.1 U49.5
D3: U49.6 U55.20
D4: U49.7 U55.19
D5: U50.15 U56.6 | length 636.3
  Top Layer w10: U56.6 7670.63,4729.37 7650,4750 7650,4865 7749.24,4964.24 U50.15
D6: U50.1 U56.5 | length 157.1
  Top Layer w10: U56.5@7895.95,4769.16 7890.84,4769.16 7880,4780 7880,4889.83 U50.1
D7: U50.2 U56.4 | length 104.2
  Top Layer w10: U50.2 7915.04,4769.75 U56.4@7915.63,4769.16
D8: U50.3 U56.3 | length 104.2
  Top Layer w10: U50.3 7934.72,4769.76 U56.3@7935.32,4769.16
D9: U50.4 U56.2 | length 104.2
  Top Layer w10: U50.4 7954.41,4769.75 U56.2@7955,4769.16
D_HV: R56.1 U62.HV | length 678.6
  Top Layer w10: R56.1 7848.3,3243.3 8095,3490 8095,3612.5 U62.HV
DDOT: U49.3 U55.3 | length 100
  Top Layer w10: U55.3 U49.3
DS3231: U1.29 U2.1 | length 138.5
  Top Layer w8: v1(10890,4880) 10891.18,4878.82 U1.29
E0: U52.2 U58.4 | length 98
  Top Layer w10: U52.2 9995.79,4777.37 U58.4
E1: U51.1 U57.5 | length 157
  Top Layer w10: U57.5 9030,4763.74 9020,4773.74 9020,4892.66 U51.1
E2: U51.2 U57.4 | length 109.3
  Top Layer w10: U57.4 9051.89,4764.41 U51.2
E3: U51.3 U57.3 | length 109.3
  Top Layer w10: U57.3 9071.57,4764.4 U51.3
E4: U51.4 U57.2 | length 109.3
  Top Layer w10: U57.2 9091.26,4764.41 U51.4
E5: U51.5 U57.1 | length 109.3
  Top Layer w10: U57.1 9110.94,4764.4 U51.5
E6: U51.6 U57.20 | length 156.6
  Top Layer w10: U51.6 9130.63,4774.37 9150,4755 9150,4724.72 U57.20
E7: U51.7 U57.19 | length 218.8
  Top Layer w10: U57.19 9179.68,4704.68 9190,4715 9190,4833.09 U51.7
E8: U52.15 U58.6 | length 595.3
  Top Layer w10: U58.6 9937.42,4735 9780,4735 9745,4770 9745,4865 9843.92,4963.92 U52.15
E9: U52.1 U58.5 | length 146.2
  Top Layer w10: U58.5 9975,4775.53 9965,4785.53 9965,4893.77 U52.1
E_HV: R57.1 U63.HV | length 710
  Top Layer w10: R57.1 9450.38,3225.38 9722.5,3497.5 U63.HV
EDOT: U51.15 U57.6 | length 614.8
  Top Layer w10: U57.6 8991.54,4725 8825,4725 8795,4755 8795,4860 8898.92,4963.92 U51.15
F0: U53.5 U59.1 | length 105.6
  Top Layer w10: U59.1 10699.84,4769.9 U53.5
F1: U52.4 U58.2 | length 98
  Top Layer w10: U52.4 10035.16,4777.37 U58.2
F2: U52.5 U58.1 | length 98
  Top Layer w10: U52.5 10056.69,4870.92 U58.1
F3: U52.6 U58.20 | length 145.5
  Top Layer w10: U52.6 10074.53,4790.47 10095,4770 10095,4737.22 U58.20
F4: U52.7 U58.19 | length 204.2
  Top Layer w10: U52.7 10135,4831.99 10135,4730 10121.47,4716.47 U58.19
F5: U53.15 U59.6 | length 612.3
  Top Layer w10: U59.6 10580.93,4730 10410,4730 10380,4760 10380,4850 10495.73,4965.73 U53.15
F6: U53.1 U59.5 | length 151.8
  Top Layer w10: U59.5 10620,4769.24 10610,4779.24 10610,4895.58 U53.1
F7: U53.2 U59.4 | length 105.6
  Top Layer w10: U59.4 10640.79,4769.91 U53.2
F8: U53.3 U59.3 | length 105.6
  Top Layer w10: U59.3 10660.47,4769.9 U53.3
F9: U53.4 U59.2 | length 105.6
  Top Layer w10: U59.2 10680.16,4769.91 U53.4
F_HV: R58.1 U64.HV | length 874.2
  Top Layer w10: R58.1 10600,3215 10845,3460 10845,3612.5 U64.HV
FDOT: U52.3 U58.3 | length 98
  Top Layer w10: U52.3 10015.47,4777.38 U58.3
G0: U44.6 U46.20 | length 150.7
  Top Layer w10: U44.6 5263.35,4786.65 5285,4765 5285,4736.06 U46.20
G1: U44.7 U46.19 | length 222
  Top Layer w10: U46.19 5313.73,4713.73 5335,4735 5335,4822.06 U44.7
G_HV: R59.1 U18.1 U19.1 | length 1080.1
  Top Layer w15: R59.1 5955.86,3245.86 6095,3385 6095,3756.73 U18.1 U19.1
GND: C1.2 C2.2 C3.2 C4.2 C5.2 C6.2 C7.2 C8.2 C9.2 C11.2 C13.2 C14.2 C20.2 C21.2 C23.1 C24.1 H2.4 H3.4 H5.3 OSC1.2 R2.1 U1.5 U2.5 U3.4 U41.8 U41.13 U41.17 U42.8 U42.13 U42.17 U44.8 U44.13 U44.17 U48.8 U48.13 U48.17 U49.8 U49.13 U49.17 U50.8 U50.13 U50.17 U51.8 U51.13 U51.17 U52.8 U52.13 U52.17 U53.8 U53.13 U53.17 U65.5 | length 2458.5
  Top Layer w10: U41.13 3679.02,4928.89 v1(3688.86,4919.05) 3698.7,4909.21 U41.8 ; U42.13 4600.16,4928.89 v1(4610,4919.05) 4619.84,4909.21 U42.8 ; U44.13 5223.98,4929.44 v1(5233.81,4919.6) 5243.65,4909.76 U44.8 ; U48.13 6329.84,4929.84 v1(6339.68,4920) 6349.52,4910.16 U48.8 ; U49.13 7317.27,4929.17 v1(7327.11,4919.33) 7336.95,4909.49 U49.8 ; U50.13 7954.41,4928.51 v1(7964.25,4918.67) 7974.09,4908.83 U50.8 ; U51.13 9091.26,4928.19 v1(9101.1,4918.35) 9110.94,4908.51 U51.8 ; U52.13 10035.16,4928.19 v1(10045,4918.35) 10054.84,4908.51 U52.8 ; U53.13 10680.16,4930 v1(10690,4920.16) 10699.84,4910.32 U53.8
  Top Layer w15: U3.4@9700,5275 9791.36,5275 C11.2 ; H3.4 10413.27,5266.73 R2.1 ; 11210.75,4657.83 U1.5@11210.75,4728.08
  Top Layer w30: C21.2 10989.74,4565.26 10965,4590 ; 11030,4690 11010,4690 10965,4645 10965,4590 ; C20.2 11211.76,4456.76 11270,4515 ; OSC1.2 11210.75,4657.83 11243.44,4657.83 11270,4631.27 11270,4515 ; 10965,4590 10965,4505 11100,4370 11205,4370 11270,4435 11270,4515
  other v1: 9900,4867.01 5093.22,4869.33 7175,4870.44 7812.28,4870.44 8959.25,4870.12 4468.27,4870.53 6195,4871.38 10550.22,4872.78 3500.75,4984.57
H0: U50.6 U56.20 | length 152.5
  Top Layer w10: U50.6 7993.78,4786.22 8015,4765 8015,4730.73 U56.20@8014.06,4729.79
H1: U50.7 U56.19 | length 222.5
  Top Layer w10: U50.7 8060,4826.56 8060,4720 8050,4710 8014.16,4710 U56.19@8014.06,4710.1
H_HV: R60.1 U20.1 U21.1 | length 1019.6
  Top Layer w10: R60.1 8843.74,3548.7 U20.1 U21.1
I2C1_SCL: U1.19 U2.2 U67.2
I2C1_SDA: U1.21 U2.3 U67.1
INFRARED-RAY: H5.2 U1.22 | length 68.4
  Top Layer w8: U1.22 v1(11147.76,5130)
LED: LED1.1 U1.23 | length 117.8
  Top Layer w15: U1.23@11116.26,5062.1 LED1.1
LIGHT_ADC: U1.7 U67.7
MOSI: U1.28 U41.14 | length 7504.4
  Top Layer w8: U41.14 3659.33,5029.33 3685,5055 10800,5055 10945,4910 11027.15,4910 U1.28@11027.99,4910.84
NIX_A0: U45.12 U47.0 | length 968.6
  Top Layer w10: U47.0 4288.43,3758.43 4460,3930 4460,4445 4560.78,4545.78 U45.12
NIX_A1: U40.11 U47.1 | length 1133.8
  Top Layer w10: U40.11 3619.96,3865.04 3864.37,3620.63 U47.1
NIX_A2: U40.12 U47.2 | length 937.7
  Top Layer w10: U40.12 3639.64,4500.36 3690,4450 3690,3900.84 U47.2
NIX_A3: U40.13 U47.3 | length 752.3
  Top Layer w10: U40.13 3659.33,4540.67 3760,4440 3760,4008.04 U47.3
NIX_A4: U40.14 U47.4 | length 567
  Top Layer w10: U40.14 3679.01,4575.99 3830,4425 3830,4115.24 U47.4
NIX_A5: U40.15 U47.5 | length 449.5
  Top Layer w10: U40.15 3901.3,4413.65 U47.5
NIX_A6: U40.16 U47.6 | length 514
  Top Layer w10: U40.16 3764.37,4655.63 4058.8,4361.2 U47.6
NIX_A7: U40.17 U47.7 | length 654.1
  Top Layer w10: U40.17 3791.63,4675.31 U47.7
NIX_A8: U45.10 U47.8 | length 629.4
  Top Layer w10: U47.8 4285.2,4433.83 U45.10
NIX_A9: U45.11 U47.9 | length 781.3
  Top Layer w10: U47.9 4380,4030.43 4380,4449.88 U45.11
NIX_ADOT: U40.10 U47.DOT | length 1501.4
  Top Layer w10: U40.10 3580.59,3769.41 3840,3510 3987.47,3510 U47.DOT
NIX_B0: U46.15 U60.0 | length 1061.6
  Top Layer w10: U46.15 5575,4283.31 5575,3940 5414.4,3779.4 U60.0
NIX_B1: U45.14 U60.1 | length 1217.6
  Top Layer w10: U45.14 4600.15,4554.85 4640,4515 4640,3935 4960,3615 5025.5,3615 U60.1
NIX_B2: U45.15 U60.2 | length 997.3
  Top Layer w10: U45.15 4695,4535.82 4695,4020 4957.2,3757.8 U60.2
NIX_B3: U45.16 U60.3 | length 840.6
  Top Layer w10: U45.16 4745,4564.56 4745,4151.6 U60.3
NIX_B4: U45.17 U60.4 | length 701.1
  Top Layer w10: U45.17 4689.97,4670.03 4815,4545 4815,4258.8 U60.4
NIX_B5: U46.10 U60.5 | length 443.8
  Top Layer w10: U60.5 5030.5,4560.3 U46.10
NIX_B6: U46.11 U60.6 | length 335.9
  Top Layer w10: U46.11 5164.25,4313.05 U60.6
NIX_B7: U46.12 U60.7 | length 432.2
  Top Layer w10: U46.12 5183.93,4411.57 U60.7
NIX_B8: U46.13 U60.8 | length 592.6
  Top Layer w10: U46.13 5203.62,4486.38 5414.4,4275.6 U60.8
NIX_B9: U46.14 U60.9 | length 834.5
  Top Layer w10: U46.14 5223.3,4526.7 5505,4245 5505,4025.6 U60.9
NIX_BDOT: U45.13 U60.DOT | length 1531.3
  Top Layer w10: U45.13 4580.47,3869.53 4945,3505 5112.3,3505 U60.DOT
NIX_C0: U55.12 U61.0 | length 957.3
  Top Layer w10: U61.0 7039.28,3771.94 7220,3952.67 7220,4505 7277.89,4562.89 U55.12
NIX_C1: U54.11 U61.1 | length 1207.4
  Top Layer w10: U54.11 6255,4600.9 6255,3955 6585,3625 6650.38,3625 U61.1
NIX_C2: U54.12 U61.2 | length 992.8
  Top Layer w10: U54.12 6290.46,4454.54 6375,4370 6375,3950 6567.2,3757.8 U61.2
NIX_C3: U54.13 U61.3 | length 805.8
  Top Layer w10: U54.13 6310.15,4519.85 6485,4345 6485,4020 6570,3935 U61.3
NIX_C4: U54.14 U61.4 | length 610.8
  Top Layer w10: U54.14 6329.83,4580.17 6586.48,4323.52 U61.4
NIX_C5: U54.15 U61.5 | length 501.7
  Top Layer w10: U54.15 6363.66,4616.68 6655.38,4324.97 U61.5
NIX_C6: U54.16 U61.6 | length 575.9
  Top Layer w10: U54.16 6423.95,4656.05 6790.7,4289.3 U61.6
NIX_C7: U54.17 U61.7 | length 757.8
  Top Layer w10: U54.17 6534.27,4675.73 6960,4250 U61.7
NIX_C8: U55.10 U61.8 | length 620
  Top Layer w10: U61.8 7039.28,4476.06 U55.10
NIX_C9: U55.11 U61.9 | length 772.4
  Top Layer w10: U61.9 7040,3935 7145,4040 7145,4503.05 U55.11
NIX_CDOT: U54.10 U61.DOT | length 1626.7
  Top Layer w10: U54.10 6210,4634.64 6210,3805 6520,3495 6727.18,3495 U61.DOT
NIX_D0: U56.15 U62.0 | length 1098.5
  Top Layer w10: U56.15@7974.69,4611.68 8013.32,4611.68 8330,4295 8330,3921.4 U62.0
NIX_D1: U55.14 U62.1 | length 1232.7
  Top Layer w10: U55.14 7317.26,4567.74 7370,4515 7370,3960 7720,3610 7772.5,3610 U62.1
NIX_D2: U55.15 U62.2 | length 1017.4
  Top Layer w10: U55.15 7465,4488.21 7465,4000 7708.6,3756.4 U62.2
NIX_D3: U55.16 U62.3 | length 863.3
  Top Layer w10: U55.16 7575,4456.95 7575,4063.6 U62.3
NIX_D4: U55.17 U62.4 | length 737
  Top Layer w10: U55.17 7429.69,4675.31 7708.6,4396.4 U62.4
NIX_D5: U56.10 U62.5 | length 438.8
  Top Layer w10: U62.5 7777.5,4571.97 U56.10@7856.58,4651.05
NIX_D6: U56.11 U62.6 | length 402.3
  Top Layer w10: U56.11@7895.95,4611.68 7825,4540.73 7825,4394.3 U62.6
NIX_D7: U56.12 U62.7 | length 439.9
  Top Layer w10: U56.12@7915.63,4611.68 7915.63,4421.87 U62.7
NIX_D8: U56.13 U62.8 | length 600.3
  Top Layer w10: U56.13@7935.32,4611.68 7935.32,4534.68 8161.4,4308.6 U62.8
NIX_D9: U56.14 U62.9 | length 861.3
  Top Layer w10: U56.14@7955,4611.68 7955,4590 8275,4270 8275,4043.6 U62.9
NIX_DDOT: U55.13 U62.DOT | length 1649.8
  Top Layer w10: U55.13 7297.58,3787.42 7625,3460 7819.3,3460 U62.DOT
NIX_E0: U58.12 U63.0 | length 950.7
  Top Layer w10: U63.0 9940,3901.4 9940,4495 9997.63,4552.63 U58.12
NIX_E1: U57.11 U63.1 | length 1240.7
  Top Layer w10: U57.11 9005,4579.72 9005,3895 9285,3615 U63.1
NIX_E2: U57.12 U63.2 | length 1031.9
  Top Layer w10: U57.12 9051.22,3938.78 9237.2,3752.8 U63.2
NIX_E3: U57.13 U63.3 | length 787.1
  Top Layer w10: U57.13 9070.91,4464.09 9220,4315 9220,4072.13 9338.6,3953.53 U63.3
NIX_E4: U57.14 U63.4 | length 601.8
  Top Layer w10: U57.14 9090.59,4534.41 9338.6,4286.4 U63.4
NIX_E5: U57.15 U63.5 | length 484.4
  Top Layer w10: U57.15 9407.5,4309.04 U63.5
NIX_E6: U57.16 U63.6 | length 565.2
  Top Layer w10: U57.16 9149.65,4645.35 9510.7,4284.3 U63.6
NIX_E7: U57.17 U63.7 | length 746.9
  Top Layer w10: U57.17 9299.69,4665.31 9720,4245 U63.7
NIX_E8: U58.10 U63.8 | length 613.4
  Top Layer w10: U63.8 9791.4,4510.24 U58.10
NIX_E9: U58.11 U63.9 | length 765.3
  Top Layer w10: U63.9 9870,4008.6 9870,4510.1 U58.11
NIX_EDOT: U57.10 U63.DOT | length 1612.7
  Top Layer w10: U57.10 8960,4613.46 8960,3840 9320,3480 9469.3,3480 U63.DOT
NIX_F0: U59.15 U64.0 | length 1081.6
  Top Layer w10: U59.15 10733.24,4611.76 11050,4295 11050,3891.4 U64.0
NIX_F1: U58.14 U64.1 | length 1285.1
  Top Layer w10: U58.14 10037,4543 10110,4470 10110,3905 10405,3610 10522.5,3610 U64.1
NIX_F2: U58.15 U64.2 | length 1047.2
  Top Layer w10: U58.15 10180,4494.74 10180,4005 10432.2,3752.8 U64.2
NIX_F3: U58.16 U64.3 | length 882.6
  Top Layer w10: U58.16 10250,4503.48 10250,4130 10450,3930 U64.3
NIX_F4: U58.17 U64.4 | length 759.2
  Top Layer w10: U58.17 10162.9,4677.1 10325,4515 10325,4240.8 U64.4
NIX_F5: U59.10 U64.5 | length 428.3
  Top Layer w10: U64.5 10527.5,4597.56 U59.10
NIX_F6: U59.11 U64.6 | length 354.2
  Top Layer w10: U59.11 10620.44,4348.86 U64.6
NIX_F7: U59.12 U64.7 | length 450.6
  Top Layer w10: U59.12 10640.12,4489.88 10842.5,4287.5 U64.7
NIX_F8: U59.13 U64.8 | length 614
  Top Layer w10: U59.13 10659.81,4540.19 10915,4285 10915,4108.6 U64.8
NIX_F9: U59.14 U64.9 | length 842.9
  Top Layer w10: U59.14 10679.49,4590.51 10990,4280 10990,4008.6 U64.9
NIX_FDOT: U58.13 U64.DOT | length 1664.1
  Top Layer w10: U58.13 10017.32,3817.68 10375,3460 10569.3,3460 U64.DOT
NIX_G0: U18.2 U46.16 | length 1178.9
  Top Layer w10: U46.16 5775,4162.05 5775,3895 5910,3760 U18.2
NIX_G1: U19.2 U46.17 | length 885.7
  Top Layer w10: U46.17 5369.89,4674.36 U19.2
NIX_H0: U20.2 U56.16 | length 1219.9
  Top Layer w10: U56.16@8014.06,4651.05 8048.95,4651.05 8415,4285 8415,4001.26 U20.2
NIX_H1: U21.2 U56.17 | length 904.5
  Top Layer w10: U56.17@8014.06,4670.73 8109.27,4670.73 8670,4110 U21.2
NRST: U1.6 U67.6
OSC_IN: C21.1 OSC1.3 U1.2 | length 194.7
  Top Layer w10: U1.2@11116.26,4728.08 11119,4725.34 OSC1.3
  Top Layer w20: C21.1 11110.3,4620.38 OSC1.3
POWER: U1.17
RADER: U1.3 U3.1 | length 1688.7
  Top Layer w8: U1.3@11147.76,4728.08 11150,4730.32 v1(11150,4865)
  Inner2 w8: U3.1 10889.46,5120.54 v1@11145,4865
RADER_RX: U1.1 U3.2 | length 1718.9
  Top Layer w8: U1.1@11084.76,4728.08 11084.76,4969.76 v1(11085,4970)
  Inner2 w8: U3.2 10899.46,5170.54 11085,4985 v1(11085,4970)
  other v1: 11300,4786.07 11300,4820
RADER_TX: U1.12 U3.3 | length 1807
  Top Layer w8: v1(11300,4880) 11361.35,4880 U1.12@11362.01,4879.34
  Inner2 w8: U3.3 9704.46,5225 10905,5225 11250,4880 v1(11300,4880)
SPI_CS: U1.20 U67.3
SPI_MOSI: U1.11 U67.5
SPI_SCK: U1.32 U67.4
SWCLK: H3.3 R2.2 U1.25 | length 731.6
  Top Layer w8: R2.2 10590.45,5100 10915,5100 11009.67,5005.33 U1.25@11027.99,5005.33
  Top Layer w15: R2.2 10475,5220.28 H3.3
SWDIO: H3.2 U1.24 | length 686.5
  Top Layer w8: H3.2 10575,5175 10620,5130 11016.86,5130 U1.24@11084.76,5062.1
SWITCH1: R45.1 U1.13 | length 9022
  Top Layer w10: R45.1 4165,3175 v1(4190,3200) ; U1.13 11424.68,4910.32 11515,4820 v1(11515,3480)
  Bottom Layer w10: v1(4190,3200) 4455,3465 11500,3465 v1(11515,3480)
SWITCH2: R46.1 U1.14 | length 8322
  Top Layer w10: R46.1 4987.6,3172.6 v1(4990,3175) ; U1.14 11438.19,4941.81 11550,4830 v1(11550,3480)
  Bottom Layer w10: v1(4990,3175) 5155,3175 5415,3435 11505,3435 v1(11550,3480)
SWITCH3: R47.1 U1.15 | length 6965.4
  Top Layer w10: R47.1 6477.82,3145 v1(6530,3145) ; U1.15 11466.69,4973.31 11620,4820 v1(11620,3475)
  Bottom Layer w10: v1(6530,3145) 6815,3145 7035,3365 11530,3365 11620,3455 v1@11620,3480
SWITCH4: R48.1 U1.16 | length 5927.2
  Top Layer w10: R48.1 7646.71,3165 v1(7705,3165) ; U1.16 11505.19,5004.81 11655,4855 v1(11655,3475)
  Bottom Layer w10: 7675,3165 v1(7705,3165) 7850,3165 8015,3330 11540,3330 11655,3445 v1(11655,3475) v1@11655,3480
SWITCH5: R49.1 U1.18 | length 4662.1
  Top Layer w10: R49.1 v1(9310,3145.58) ; U1.18 11273.74,5128.74 11295,5150 11415,5150 11710,4855 v1(11710,3475)
  Bottom Layer w10: v1(9310,3145.58) 9650.58,3145.58 9765,3260 11570,3260 11710,3400 v1(11710,3475)
SWITCH6: R50.1 U1.8 | length 2776.8
  Top Layer w10: R50.1 11341.37,3146.37 11400,3205 11400,4665 11336.92,4728.08 U1.8@11305.24,4728.08
pads on no net: OSC1.1 U40.7 U40.18 U45.7 U45.18 U46.7 U46.18 U53.6 U53.7 U53.9 U54.7 U54.18 U55.7 U55.18 U56.7 U56.18 U57.7 U57.18 U58.7 U58.18 U59.7 U59.16 U59.17 U59.18 U59.19 U59.20

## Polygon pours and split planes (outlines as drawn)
170_GND on Bottom Layer (solid, remove dead copper, pour order 0): 3400,4615 5665,4615 5740,4690 5890,4690 5975,4605 10725,4605 10755,4635 10755,4825 10755.04,4830 3400,4830

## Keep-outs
Board Outline Layer:
  circle w1: c5810,4515 r59.06
  region: 5869.06,4515 cw(c5810,4515) 5750.94,4515 cw(c5810,4515)
  lines w10: 3000,3200 3000,5175 3199.01,5175 3199.01,5375 11555.16,5375 11555.16,5182.83 11756.85,5183.15 11760,3200 11556.61,3200 11556.61,3000 3200,3000 3200,3200 3000,3200

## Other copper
Top Layer:
  region net $1N7662: 3547.42,4675.31 3527.11,4655 3510,4655 3510,4695 3527.73,4695

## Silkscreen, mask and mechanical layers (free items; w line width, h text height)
Mechanical Layer:
  circle w1: c5810,4515 r59.06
